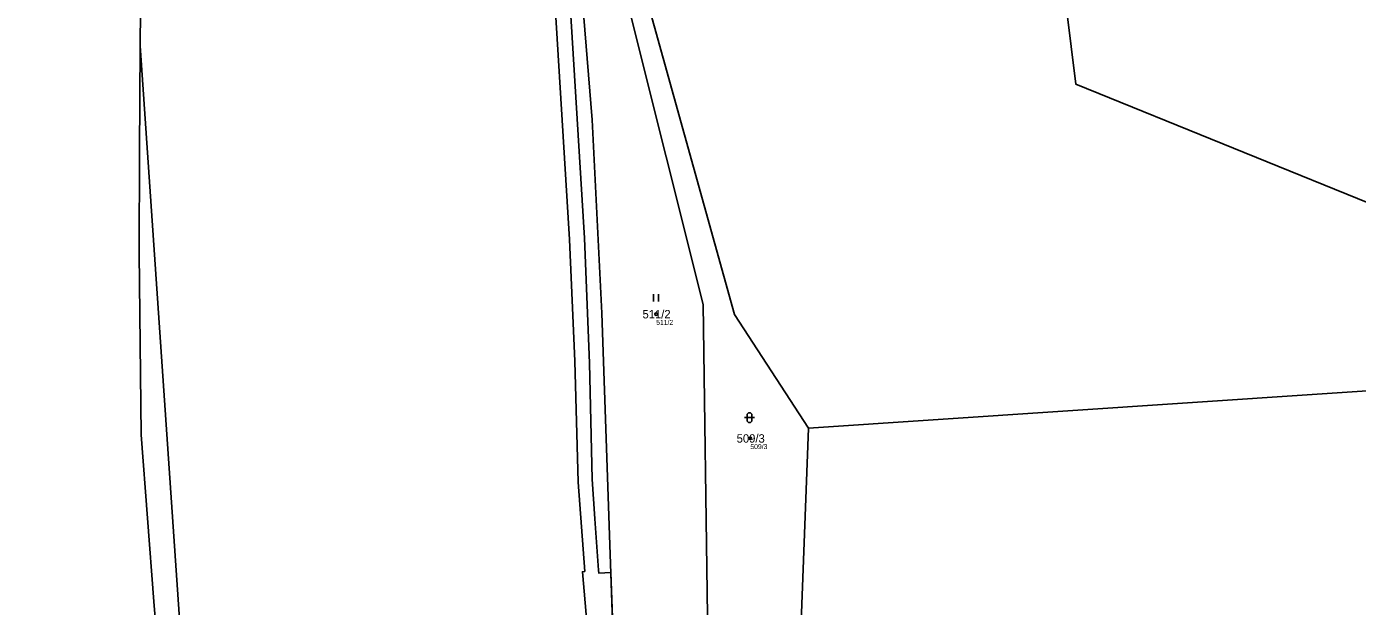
# Model space of a CAD drawing. Extents: x -766177 to -763254, y -1057727 to -1053915.
# Drawn here: x -765752 to -765482.3, y -1056112.4 to -1055995 of the extents above; entities that cross this region are included whole.
import ezdxf

# ---------------------------------------------------------------- set-up
doc = ezdxf.new("R2010")
doc.units = 0
for name, color, linetype in [('Vrstva 1', 7, 'Continuous'), ('Vrstva 13', 7, 'Continuous'), ('Vrstva 2', 7, 'Continuous'), ('Vrstva 3', 7, 'Continuous'), ('Vrstva 50', 7, 'Continuous'), ('Vrstva 51', 7, 'Continuous'), ('Vrstva 53', 7, 'Continuous')]:
    doc.layers.add(name, color=color, linetype=linetype)

msp = doc.modelspace()

# ---------------------------------------------------------------- linework, layer by layer
at = {"layer": 'Vrstva 1'}
msp.add_line((-765595.04, -1056115.54), (-765593.55, -1056076.37), dxfattribs=at)
for points in [[(-765393.26, -1056031.51), (-765411.71, -1056027.54), (-765438.99, -1056033.2), (-765475.45, -1056032.58), (-765539.39, -1056006.66), (-765543.08, -1055976.66), (-765526.71, -1055977.54), (-765576.93, -1055947.5), (-765577.6, -1055904.96), (-765565.41, -1055877.76)], [(-765593.55, -1056076.37), (-765608.54, -1056053.34), (-765626.95, -1055987.06), (-765637.2, -1055935.18), (-765645.42, -1055923.21)], [(-765644.86, -1055931.59), (-765614.84, -1056051.27), (-765614, -1056114.31), (-765603.2, -1056116.09)], [(-765644.86, -1055931.59), (-765640.58, -1055974.07), (-765637.37, -1056013.87), (-765635.4, -1056053.04), (-765633.16, -1056117.5)], [(-765728.43, -1055980.3), (-765728.79, -1055984.35), (-765728.95, -1055998.9)], [(-765728.95, -1055998.9), (-765729.1, -1056020.38), (-765729.16, -1056040.93)], [(-765728.95, -1055998.9), (-765702.47, -1056384.38), (-765699.85, -1056412.75), (-765690.44, -1056560.71), (-765692.93, -1056561.02), (-765692.24, -1056570.88)], [(-765393.26, -1056031.51), (-765387.38, -1056062.54), (-765593.55, -1056076.37)], [(-765729.16, -1056040.93), (-765728.73, -1056077.66), (-765726.15, -1056111.43), (-765722.95, -1056151.55), (-765715.51, -1056262.47), (-765706.37, -1056392.79)]]:
    msp.add_lwpolyline(points, dxfattribs=at)
at = {"layer": 'Vrstva 13'}
for points in [[(-765644.71, -1055993.14), (-765641.96, -1056038.12), (-765640.87, -1056062.79), (-765640.21, -1056087.25), (-765638.86, -1056105.33), (-765639.33, -1056105.42), (-765636.99, -1056132.9)], [(-765633.26, -1056114.67), (-765633.58, -1056105.54), (-765636.04, -1056105.68), (-765636.11, -1056105.1), (-765636.83, -1056094.67), (-765637.38, -1056086.68), (-765637.91, -1056063.15), (-765638.89, -1056037.87), (-765641.69, -1055992.84)]]:
    msp.add_lwpolyline(points, dxfattribs=at)
at = {"layer": 'Vrstva 3'}
for p, q in [((-765624.941, -1056050.72), (-765624.941, -1056049.22)), ((-765623.94, -1056050.72), (-765623.94, -1056049.22)), ((-765606.481, -1056074.211), (-765604.479, -1056074.211)), ((-765605.981, -1056073.711), (-765605.981, -1056074.712)), ((-765604.979, -1056074.712), (-765604.979, -1056073.711))]:
    msp.add_line(p, q, dxfattribs=at)
for centre, start, end in [((-765605.48, -1056073.7109), 0, 180), ((-765605.48, -1056074.7109), 180, 359.9878861)]:
    msp.add_arc(centre, 0.5, start, end, dxfattribs=at)
at = {"layer": 'Vrstva 50'}
for centre in [(-765624.39, -1056053.25994), (-765605.31, -1056078.41994)]:
    msp.add_circle(centre, 0.25, dxfattribs=at)
at = {"layer": 'Vrstva 51'}
for points in [[(-765751.96, -1055706.4), (-765740.65, -1055768.53), (-765734.28, -1055803.55), (-765730.3, -1055845.45), (-765728.18, -1055876), (-765725.07, -1055901.58), (-765722.12, -1055926.68), (-765725.18, -1055950.07), (-765727, -1055964.04), (-765726.45, -1055970.82), (-765728.43, -1055980.3), (-765728.79, -1055984.35), (-765728.95, -1055998.9), (-765702.47, -1056384.38)], [(-765616.86, -1056427.33), (-765624.14, -1056305.28), (-765625.47, -1056282.85), (-765626.25, -1056263.32), (-765627.11, -1056245.09), (-765628.71, -1056223.4), (-765631.05, -1056178.46), (-765632.41, -1056132.45), (-765633.16, -1056117.5), (-765635.4, -1056053.04), (-765637.37, -1056013.87), (-765640.58, -1055974.07), (-765644.86, -1055931.59), (-765645.42, -1055923.21)], [(-765702.47, -1056384.38), (-765728.95, -1055998.9), (-765729.1, -1056020.38), (-765729.16, -1056040.93), (-765728.73, -1056077.66), (-765726.15, -1056111.43), (-765722.95, -1056151.55), (-765715.51, -1056262.47), (-765706.37, -1056392.79)], [(-765387.38, -1056062.54), (-765593.55, -1056076.37), (-765595.04, -1056115.54), (-765594.08, -1056135.28), (-765593.79, -1056140.24), (-765593.56, -1056144.25), (-765593.32, -1056148.57), (-765593.09, -1056152.65), (-765592.73, -1056159.02), (-765592.26, -1056165.49), (-765591.51, -1056176.31), (-765589.69, -1056213.7), (-765587.29, -1056223.01), (-765580.6, -1056242.74), (-765575.21, -1056263.26), (-765575.2, -1056281.14), (-765573.05, -1056280.75), (-765572.07, -1056285.87), (-765574.79, -1056286.41), (-765567.96, -1056317.23)]]:
    msp.add_lwpolyline(points, dxfattribs=at)
for points in [[(-765411.71, -1056027.54), (-765438.99, -1056033.2), (-765475.45, -1056032.58), (-765539.39, -1056006.66), (-765543.08, -1055976.66), (-765526.71, -1055977.54), (-765576.93, -1055947.5), (-765577.6, -1055904.96), (-765565.41, -1055877.76), (-765654.53, -1055834.76), (-765655.71, -1055839.38), (-765647.38, -1055921.67), (-765645.5, -1055922.01), (-765645.42, -1055923.21), (-765637.2, -1055935.18), (-765626.95, -1055987.06), (-765608.54, -1056053.34), (-765593.55, -1056076.37), (-765387.38, -1056062.54), (-765393.26, -1056031.51)], [(-765472.22, -1055928.35), (-765500.8, -1055914.61), (-765528.9, -1055896.66), (-765565.41, -1055877.76), (-765577.6, -1055904.96), (-765576.93, -1055947.5), (-765526.71, -1055977.54), (-765543.08, -1055976.66), (-765539.39, -1056006.66), (-765475.45, -1056032.58), (-765438.99, -1056033.2), (-765411.71, -1056027.54), (-765393.26, -1056031.51), (-765388.87, -1055998.98), (-765385.72, -1055984.71), (-765389.18, -1055961), (-765436.46, -1055942.74)], [(-765637.2, -1055935.18), (-765645.42, -1055923.21), (-765644.86, -1055931.59), (-765614.84, -1056051.27), (-765614, -1056114.31), (-765603.2, -1056116.09), (-765595.04, -1056115.54), (-765593.55, -1056076.37), (-765608.54, -1056053.34), (-765626.95, -1055987.06)], [(-765640.58, -1055974.07), (-765637.37, -1056013.87), (-765635.4, -1056053.04), (-765633.16, -1056117.5), (-765621.18, -1056116.94), (-765603.2, -1056116.09), (-765614, -1056114.31), (-765614.84, -1056051.27), (-765644.86, -1055931.59)]]:
    msp.add_lwpolyline(points, close=True, dxfattribs=at)
at = {"layer": 'Vrstva 53'}
msp.add_lwpolyline([(-765751.96, -1055706.4), (-765740.65, -1055768.53), (-765734.28, -1055803.55), (-765730.3, -1055845.45), (-765728.18, -1055876), (-765725.07, -1055901.58), (-765722.12, -1055926.68), (-765725.18, -1055950.07), (-765727, -1055964.04), (-765728.43, -1055980.3), (-765728.79, -1055984.35), (-765728.95, -1055998.9), (-765729.1, -1056020.38), (-765729.16, -1056040.93), (-765728.73, -1056077.66), (-765726.15, -1056111.43), (-765722.95, -1056151.55), (-765715.51, -1056262.47), (-765706.37, -1056392.79)], dxfattribs=at)

# ---------------------------------------------------------------- texts
at = {"layer": 'Vrstva 2'}
for s, p in [('511/2', (-765627.163, -1056054.11)), ('509/3', (-765608.083, -1056079.27))]:
    msp.add_text(s, height=1.699998, dxfattribs=at).set_placement(p)
at = {"layer": 'Vrstva 50'}
for s, p in [('511/2', (-765624.39, -1056055.416)), ('509/3', (-765605.31, -1056080.576))]:
    msp.add_text(s, height=0.999996, dxfattribs=at).set_placement(p)

doc.saveas('drawing.dxf')
